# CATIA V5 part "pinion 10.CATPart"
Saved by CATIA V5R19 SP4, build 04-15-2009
Part number: pinion 10
Bounding box of the stored display mesh (mm): x 0 to 22.15, y -45.242 to 45.242, z -45.049 to 45.049
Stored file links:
  G:\EU_thinkMotion\CFAO_2010\MMS_groupe1\MMS_groupe1\A reprendre\OK\rdeneffle\pinion 10.CATPart
  G:\EU_thinkMotion\CFAO_2010\MMS_groupe1\MMS_groupe1\A reprendre\OK\rdeneffle\pinion 2.CATPart
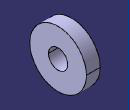
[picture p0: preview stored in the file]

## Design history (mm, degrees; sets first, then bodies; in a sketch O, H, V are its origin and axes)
Parameters
  `rayon interieur` = 15.505 mm
  `rayon extérieur` = 35.556 mm
  `rayon interieur.1` = 15.505 mm
  `rayon extérieur.1` = 45.242 mm
Body1 (main body)
Body2
  Sketch1 on yz-plane, origin (0, 0, 0), H (0, 1, 0), V (0, 0, 1)
    circle A1 centre (0, 0) radius 15.505
    circle A2 centre (0, 0) radius 45.242
    radius A2 = 45.242 {= `rayon extérieur.1`}
    radius A1 = 15.505 {= `rayon interieur.1`}
  Pad1: profile Sketch1, direction (1, 0, 0), length 22.15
